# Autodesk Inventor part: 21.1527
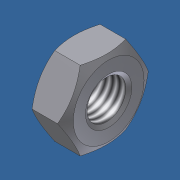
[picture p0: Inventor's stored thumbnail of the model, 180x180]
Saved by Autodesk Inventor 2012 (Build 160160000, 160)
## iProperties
Created: 2006-02
Part Number: 21.1527
Material: Steel, Mild
Description: M10 HEX NUT
Document SubType Name: Modeling
Standard: DIN 934
Designer: Andy Moles
Standards Organization: DIN
Language: en-US
Size Designation: M10
Categories: <MemberInstance><Categories><Category DisplayName="Fasteners" InternalName="e4da775c-781d-43d5-af7c-5136215cf5a6" Mnemonic="FSTN"><Category DisplayName="Nuts" I
Mass: 11.7561 g
Surface Area: 9.86681 cm^2
Volume: 1.49568 cm^3
Density: 7.86 g/cm^3
Author: Andy Moles
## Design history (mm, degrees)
body "Solid1"
workaxis "Work Axis1"
workplane "Work Plane1"
sketch "Sketch1"
  geometry: L1 (-9.815, 0)-(-4.907, 8.5); L2 (-4.907, 8.5)-(4.907, 8.5); L3 (4.907, 8.5)-(9.815, 0); L4 (9.815, 0)-(4.907, -8.5); L5 (4.907, -8.5)-(-4.907, -8.5); L6 (-4.907, -8.5)-(-9.815, 0); 2 further points
  constraints: 12 end point, 1 coincident, 1 horizontal, 11 other
  dimensions: "d0" = 19.62991 distance of L3.end L1.start (= 1.1547 x SW)
extrude "Body" new body sketch "Sketch1" distance "d1" = 8 (= KOH); taper "d2" = 0 deg
revolve "Chamfer1" stored, may be unused: angle "d7" = 90 deg
sketch "Sketch3"
  geometry: 4 further points
  constraints: 1 coincident, 1 other
hole "Thread" sketch "Sketch3" diameter "d25" = 8.376; stored, may be unused: countersink angle "d29" = 82 deg, drill point angle "d31" = 118 deg; dims "d26" = 6, "d27" = 4, "d28" = 2, "d30" = 8
chamfer "Chamfer2" distance "d8" = 0.8119 (= -0.5 x GD1 + 0.5 x NND); stored, may be unused: angle "d9" = 30 deg, second distance "d40" = 0.8119 (= -0.5 x GD1 + 0.5 x NND)
chamfer "Chamfer3" distance "d10" = 0.8119 (= -0.5 x GD1 + 0.5 x NND); stored, may be unused: angle "d11" = 30 deg, second distance "d41" = 0.8119 (= -0.5 x GD1 + 0.5 x NND)
sketch "Sketch2"
  geometry: L1 (0, 4.907)-(0, 9.815) reference; L2 (0, 9.815)-(8, 9.815) reference; L3 (8, 4.907)-(8, 9.815) reference; L4 (-0.8, 0)-(10.4, 0) reference; L5 (1.25, 9.815)-(0, 7.65); L6 (6.75, 9.815)-(8, 7.65)
  constraints: 4 end point, 4 point on line
  dimensions: "d3" = 30 deg angle of L1 L5 (= ANG1); "d4" = 30 deg angle of L3 L6 (= ANG2); "d5" = 15.3 diameter of L5.end L4 (= SW0); "d6" = 15.3 diameter of L6.end L4 (= SW01)
other parameters: "ANG1" = 30 deg [user parameter; used in 1 equation term], "ANG2" = 30 deg [user parameter; used in 1 equation term], "KOH" = 8 [user parameter; used in 1 equation term], "SW" = 17 [user parameter; used in 2 equation terms], "SW0" = 15.3 (= SW01) [user parameter; used in 1 equation term], "SW01" = 15.3 [user parameter; used in 2 equation terms], "GD1" = 8.3762 (computed from THREADDIA, PTC, TOA) [user parameter; used in 4 equation terms], "d13" = 0, "d14" = 0, "d39" = 0, "d42" = 0, "GUL" = 0.8119 (= 0.541266 x PTC) [user parameter], "TPU" = 6.66667 (computed from PTC) [user parameter], "TOA" = 30 deg [user parameter; used in 1 equation term], "PTC" = 1.5 [user parameter; used in 4 equation terms], "E0" = 19.635 (= 1.155 x SW) [user parameter], "GAL" = 0.8119 (= 0.541266 x PTC) [user parameter]
